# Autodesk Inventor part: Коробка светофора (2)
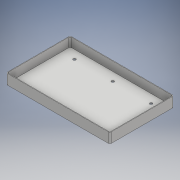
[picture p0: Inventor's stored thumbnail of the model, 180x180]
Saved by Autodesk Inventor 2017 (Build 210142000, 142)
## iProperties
Part Number: Коробка светофора (2)
Material: Типовые
Document SubType Name: Modeling
Designer: Система Знаний
Density: 1 g/cm^3
Appearance: По умолчанию
Author: Система Знаний
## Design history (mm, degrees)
sketch "Эскиз1"
  geometry: L1 (0, 0)-(314, 0); L2 (314, 0)-(314, -194); L3 (314, -194)-(0, -194); L4 (0, -194)-(0, 0)
  constraints: 8 end point, 2 parallel, 1 horizontal, 1 perpendicular
  dimensions: "d0" = 314 distance of L2.end L3.end; "d1" = 194 distance of L1.end L2.end
extrude "Выдавливание1" new body sketch "Эскиз1" distance "d2" = 29; taper "d3" = 0 deg
feature "Оболочка1" dims "d4" = 1.7
sketch "Эскиз4"
  geometry: L1 (-314, -194)-(0, -194) reference; L2 (0, 0)-(-314, 0); L3 (-314, 0)-(-314, -194); L4 (-314, -194)-(0, -194); L5 (0, -194)-(0, 0); 1 further point
  constraints: 8 end point, 2 parallel, 1 horizontal, 1 perpendicular
extrude "Выдавливание3" join sketch "Эскиз4" distance "d12" = 1.3; taper "d13" = 0 deg
fillet "Сопряжение6" dims "d14" = 5
fillet "Сопряжение7" dims "d15" = 5
sketch "Эскиз5"
  geometry: L1 (0, -189)-(0, -5) reference; L2 (0, -189)-(0, -5) reference; C1 r 4 at (-157, -28); C2 r 4 at (-41, -28); C3 r 4 at (-273, -28); 2 further points
  constraints: 3 centre point, 1 coincident
hole "Отверстие1" sketch "Эскиз5" at (-157, -28) diameter "d27" = 8; stored, may be unused: countersink angle "d31" = 90 deg, drill point angle "d33" = 118 deg; dims "d28" = 6, "d29" = 4, "d30" = 2, "d32" = 8
sketch "Эскиз6"
  geometry: L1 (0, -189)-(0, -5) reference; L2 (0, -189)-(0, -5) reference; C1 r 4 at (-157, -28) reference; C2 r 4 at (-41, -28); C3 r 4 at (-273, -28); 2 further points
  constraints: 2 centre point, 1 coincident
  dimensions: "d38" = 8 diameter of C2; "d39" = 8 diameter of C3
hole "Отверстие2" sketch "Эскиз6" at (-273, -28), (-41, -28) diameter "d40" = 8; stored, may be unused: countersink angle "d44" = 90 deg, drill point angle "d46" = 118 deg; dims "d41" = 6, "d42" = 10, "d43" = 2, "d45" = 8
node "Твердое тело1"
other parameters: "sa_0" = 4
